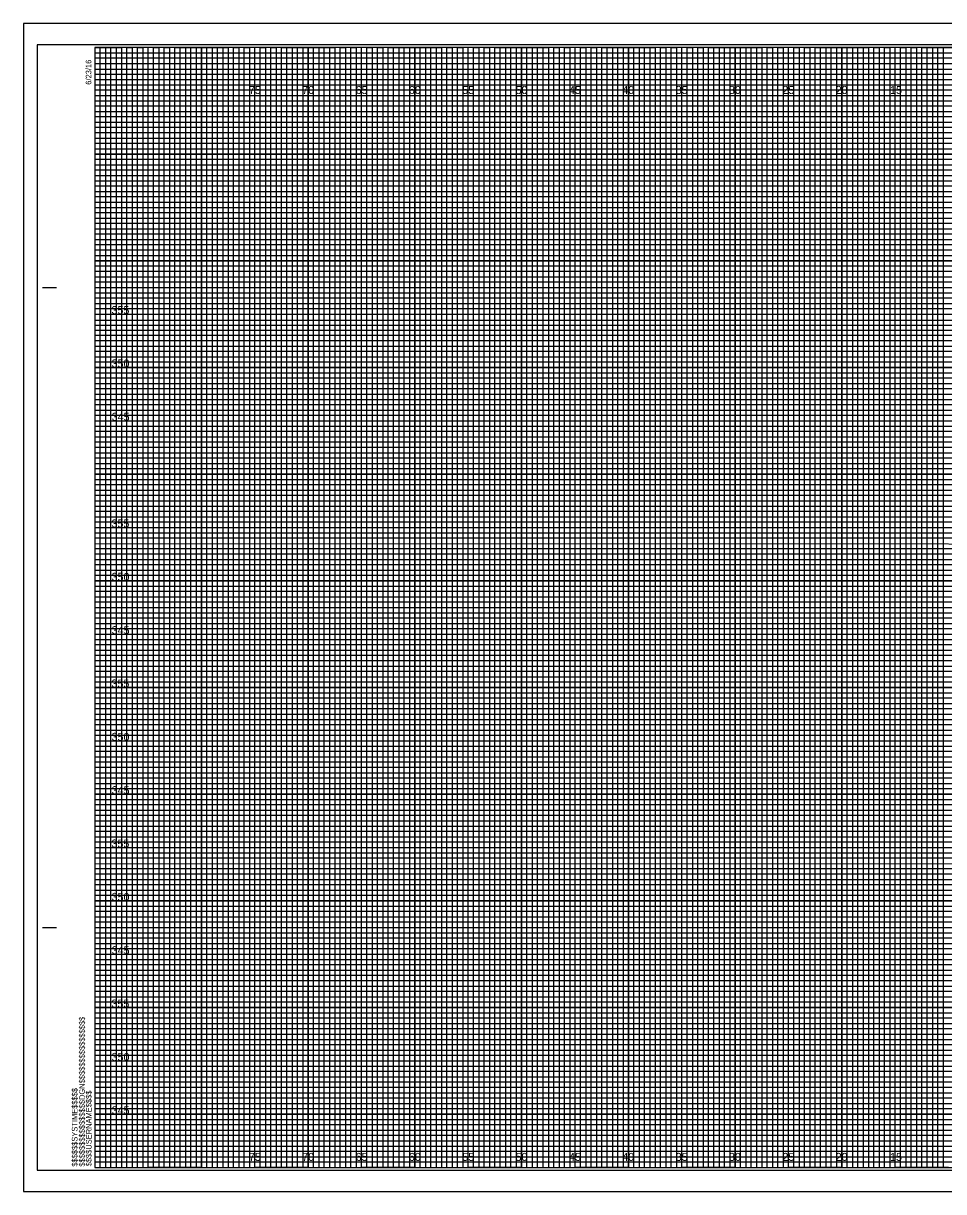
# Model space of a CAD drawing. Extents: x -7 to 166, y 218 to 327.
# Drawn here: x -6.7 to 79.5, y 217.7 to 327.2 of the extents above; entities that cross this region are included whole.
import ezdxf

# ---------------------------------------------------------------- set-up
doc = ezdxf.new("R2010")
doc.units = 0
for name, color, linetype in [('Prop XS Elevation Labels', 7, 'Continuous'), ('Prop XS Offset Labels', 7, 'Continuous'), ('Sheet Cross Section CELL', 7, 'Continuous'), ('Sheet Cross Section Grid Major CELL', 7, 'Continuous'), ('Sheet Cross Section Grid Middle CELL', 7, 'Continuous'), ('Sheet Cross Section Grid Minor 1 CELL', 7, 'Continuous'), ('Sheet Cross Section Grid Minor 2 CELL', 7, 'Continuous'), ('Sheet Cutting Line CELL', 7, 'Continuous'), ('Sheet DOT Grid CELL', 7, 'Continuous'), ('Sheet Plot Border Inside CELL', 7, 'Continuous'), ('Sheet Plot Border Outside CELL', 7, 'Continuous')]:
    doc.layers.add(name, color=color, linetype=linetype)

msp = doc.modelspace()

# ---------------------------------------------------------------- linework, layer by layer
at = {"layer": 'Sheet Cross Section CELL'}
for p, q in [((-4.9, 302.5), (-3.65, 302.5)), ((-4.85, 302.5), (-3.6, 302.5)), ((-4.9, 242.5), (-3.65, 242.5)), ((-4.85, 242.5), (-3.6, 242.5)), ((0, 220), (0, 220)), ((0, 220), (0, 220)), ((0, 220), (0, 220)), ((0, 220), (0, 220)), ((0, 220), (0, 220)), ((0, 220), (0, 220)), ((0, 220), (0, 220))]:
    msp.add_line(p, q, dxfattribs=at)
msp.add_lwpolyline([(160, 325), (0, 325), (0, 220), (160, 220)], close=True, dxfattribs=at)
at = {"layer": 'Sheet Cross Section Grid Major CELL'}
for p, q in [((5, 325), (0, 325)), ((5, 220), (5, 325)), ((15, 325), (10, 325)), ((10, 325), (10, 220)), ((15, 220), (15, 325)), ((25, 325), (20, 325)), ((20, 325), (20, 220)), ((25, 220), (25, 325)), ((35, 325), (30, 325)), ((30, 325), (30, 220)), ((35, 220), (35, 325)), ((45, 325), (40, 325)), ((40, 325), (40, 220)), ((45, 220), (45, 325)), ((55, 325), (50, 325)), ((50, 325), (50, 220)), ((55, 220), (55, 325)), ((65, 325), (60, 325)), ((60, 325), (60, 220)), ((65, 220), (65, 325)), ((75, 325), (70, 325)), ((70, 325), (70, 220)), ((75, 220), (75, 325)), ((10, 220), (5, 220)), ((20, 220), (15, 220)), ((30, 220), (25, 220)), ((40, 220), (35, 220)), ((50, 220), (45, 220)), ((60, 220), (55, 220)), ((70, 220), (65, 220)), ((80, 220), (75, 220))]:
    msp.add_line(p, q, dxfattribs=at)
for points in [[(0, 320), (160, 320), (160, 315), (0, 315)], [(0, 310), (160, 310), (160, 305), (0, 305)], [(0, 300), (160, 300), (160, 295), (0, 295)], [(0, 290), (160, 290), (160, 285), (0, 285)], [(0, 280), (160, 280), (160, 275), (0, 275)], [(0, 270), (160, 270), (160, 265), (0, 265)], [(0, 260), (160, 260), (160, 255), (0, 255)], [(0, 250), (160, 250), (160, 245), (0, 245)], [(0, 240), (160, 240), (160, 235), (0, 235)], [(0, 230), (160, 230), (160, 225), (0, 225)]]:
    msp.add_lwpolyline(points, dxfattribs=at)
at = {"layer": 'Sheet Cross Section Grid Middle CELL'}
for points in [[(0, 325), (2.5, 325), (2.5, 220), (7.5, 220), (7.5, 325), (12.5, 325), (12.5, 220), (17.5, 220), (17.5, 325), (22.5, 325), (22.5, 220), (27.5, 220), (27.5, 325), (32.5, 325), (32.5, 220), (37.5, 220), (37.5, 325), (42.5, 325), (42.5, 220), (47.5, 220), (47.5, 325), (52.5, 325), (52.5, 220), (57.5, 220), (57.5, 325), (62.5, 325), (62.5, 220), (67.5, 220), (67.5, 325), (72.5, 325), (72.5, 220), (77.5, 220), (77.5, 325), (82.5, 325)], [(0, 322.5), (137.5, 322.5)], [(0, 312.5), (160, 312.5), (160, 317.5), (0, 317.5)], [(0, 302.5), (160, 302.5), (160, 307.5), (0, 307.5)], [(0, 292.5), (160, 292.5), (160, 297.5), (0, 297.5)], [(0, 282.5), (160, 282.5), (160, 287.5), (0, 287.5)], [(0, 272.5), (160, 272.5), (160, 277.5), (0, 277.5)], [(0, 262.5), (160, 262.5), (160, 267.5), (0, 267.5)], [(0, 252.5), (160, 252.5), (160, 257.5), (0, 257.5)], [(0, 242.5), (160, 242.5), (160, 247.5), (0, 247.5)], [(0, 232.5), (160, 232.5), (160, 237.5), (0, 237.5)], [(0, 222.5), (160, 222.5), (160, 227.5), (0, 227.5)]]:
    msp.add_lwpolyline(points, dxfattribs=at)
at = {"layer": 'Sheet Cross Section Grid Minor 1 CELL'}
for p, q in [((0, 324.5), (130, 324.5)), ((130, 323.99), (0, 323.99)), ((0, 323.99), (0, 323.5)), ((0, 323.5), (130, 323.5)), ((130, 322.94), (0, 322.94)), ((0, 322.94), (0, 322)), ((0, 322), (160, 322))]:
    msp.add_line(p, q, dxfattribs=at)
for points in [[(0, 321.5), (135, 321.5), (160, 321.5), (160, 321), (0, 321)], [(0, 320.5), (160, 320.5), (160, 319.5), (0, 319.5)], [(0, 319), (160, 319), (160, 318.5), (0, 318.49)], [(0, 318), (160, 318), (160, 317), (0, 317)], [(0, 316.5), (160, 316.5), (160, 316), (0, 316)], [(0, 315.5), (160, 315.5), (160, 314.5), (0, 314.5)], [(0, 314), (160, 314), (160, 313.5), (0, 313.5)], [(0, 313), (160, 313), (160, 312), (0, 312)], [(0, 311.5), (160, 311.5), (160, 311), (0, 311)], [(0, 310.5), (160, 310.5), (160, 309.5), (0, 309.5)], [(0, 309), (160, 309), (160, 308.5), (0, 308.5)], [(0, 308), (160, 308), (160, 306.98), (160, 306.5), (160, 306), (0, 306)], [(0, 307), (160, 307), (160, 306.5), (0, 306.5)], [(0, 305.5), (160, 305.5), (160, 304.5), (0, 304.51)], [(0, 304.51), (160, 304.5), (160, 304), (0, 304)], [(0, 303.5), (160, 303.5), (160, 303), (0, 303)], [(0, 302), (160, 302), (160, 301.5), (0, 301.5)], [(0, 301), (160, 301), (160, 300.5), (0, 300.5)], [(-0.04, 299.44), (160, 299.44), (160, 298.94), (-0.04, 298.94)], [(0, 298.5), (160, 298.5), (160, 298), (0, 298)], [(0, 297), (160, 297), (160, 296.5), (0, 296.5)], [(0, 296), (160, 296), (160, 295.5), (0, 295.5)], [(0, 294.5), (160, 294.5), (160, 294), (0, 294)], [(0, 293.5), (160, 293.5), (160, 293), (0, 293)], [(0, 292), (160, 292), (160, 291.5), (0, 291.5)], [(0, 291), (160, 291), (160, 290.5), (0, 290.5)], [(0, 289.5), (160, 289.5), (160, 288.99), (0, 289)], [(0, 288.5), (160, 288.5), (160, 288), (0, 288)], [(0, 287), (160, 287), (160, 286.5), (0, 286.5)], [(0, 286), (160, 286), (160, 285.5), (0, 285.5)], [(0, 284.5), (160, 284.5), (160, 284), (0, 284)], [(0, 283.5), (160, 283.5), (160, 283), (0, 283)], [(0, 282), (160, 282), (160, 281.5), (0, 281.5)], [(0, 281), (160, 281), (160, 280.5), (0, 280.5)], [(0, 279.5), (160, 279.5), (160, 279), (0, 279)], [(0, 278.5), (160.03, 278.45), (160, 278), (0, 278)], [(0, 277), (160, 277), (160, 276.5), (0, 276.5)], [(0, 276), (160, 276), (160, 275.5), (0, 275.5)], [(0, 274.5), (160, 274.5), (160, 274), (0, 274)], [(0, 273.5), (160, 273.5), (160, 273), (0, 273)], [(0, 272), (160, 272), (160, 271.5), (0, 271.5)], [(0, 271), (160, 271), (160, 270.5), (0, 270.5)], [(0, 269.5), (160, 269.5), (160, 269), (0, 269)], [(0, 268.5), (160, 268.5), (160, 268), (0, 268)], [(0, 267), (160, 267), (160, 266.5), (0, 266.5)], [(0, 266), (160, 266), (160, 265.5), (0, 265.5)], [(0, 264.5), (160, 264.5), (160, 264), (0, 264)], [(0, 263.5), (160, 263.5), (160, 263), (0, 263)], [(0, 262), (160, 262), (160, 261.5), (0, 261.5)], [(0, 261), (160, 261), (160, 260.5), (0, 260.5)], [(0, 259.5), (160, 259.5), (160, 258.99), (0, 259)], [(0, 258.5), (160, 258.5), (160, 258), (0, 258)], [(0, 257), (160, 257), (160, 256.5), (0, 256.5)], [(0, 256), (160, 256), (160, 255.5), (0, 255.5)], [(0, 254.5), (160, 254.5), (160, 254), (0, 254)], [(0, 253.5), (160, 253.5), (160, 253), (0, 253)], [(0, 252), (160, 252), (160, 251.5), (0, 251.5)], [(0, 251), (160, 251), (160, 250.5), (0, 250.5)], [(0, 249.5), (160, 249.5), (160, 249), (0, 249)], [(0, 248.5), (160.03, 248.46), (160, 248), (0, 248)], [(0, 247), (160, 247), (160, 246.5), (0, 246.5)], [(0, 246), (160, 246), (160, 245.5), (0, 245.5)], [(0, 244.5), (160, 244.5), (160, 244), (0, 244)], [(0, 243.5), (160, 243.5), (160, 243), (0, 243)], [(0, 242), (160, 242), (160, 241.5), (0, 241.5)], [(0, 241), (160, 241), (160, 240.5), (0, 240.5)], [(0, 239.5), (160, 239.5), (160, 239), (0, 239)], [(0, 238.5), (160, 238.5), (160, 238), (0, 238)], [(0, 237), (160, 237), (160, 236.5), (0, 236.5)], [(0, 236), (160, 236), (160, 235.5), (0, 235.5)], [(0, 234.5), (160, 234.5), (160, 234), (0, 234)], [(0, 233.5), (160, 233.5), (160, 233), (0, 233)], [(0, 232), (160, 232), (160, 231.5), (0, 231.5)], [(0, 231), (160, 231), (160, 230.5), (0, 230.5)], [(0, 229.5), (160, 229.5), (160, 229), (0, 229)], [(0, 228.5), (160, 228.5), (160, 228), (0, 228)], [(0, 227), (160, 227), (160, 226.5), (0, 226.5)], [(0, 226), (160, 226), (160, 225.5), (0, 225.5)], [(0, 224.5), (160, 224.5), (160, 224), (0, 224)], [(0, 223.5), (160, 223.5), (160, 223), (0, 223)], [(0, 222), (160, 222), (160, 221.5), (0, 221.5)], [(0, 221), (160, 221), (160, 220.5), (0, 220.5)]]:
    msp.add_lwpolyline(points, dxfattribs=at)
at = {"layer": 'Sheet Cross Section Grid Minor 2 CELL'}
for points in [[(0, 220), (0.5, 220), (0.5, 325), (1, 325), (1, 220)], [(1, 220), (1.5, 220), (1.5, 325), (2, 325), (2, 220)], [(2.5, 220), (3, 220), (3, 325), (3.5, 325), (3.5, 220)], [(3.5, 220), (4, 220), (4, 325), (4.5, 325), (4.5, 220)], [(5, 220), (5.5, 220), (5.5, 325), (6, 325), (6, 220)], [(6, 220), (6.5, 220), (6.5, 325), (7, 325), (7, 220)], [(7.5, 220), (8, 220), (8, 325), (8.5, 325), (8.5, 220)], [(8.5, 220), (9, 220), (9, 325), (9.5, 325), (9.5, 220)], [(10, 220), (10.5, 220), (10.5, 325), (11, 325), (11, 220)], [(11, 220), (11.5, 220), (11.5, 325), (12, 325), (12, 220)], [(12.5, 220), (13, 220), (13, 325), (13.5, 325), (13.5, 220)], [(13.5, 220), (14, 220), (14, 325), (14.5, 325), (14.5, 220)], [(15, 220), (15.5, 220), (15.5, 325), (16, 325), (16, 220)], [(16, 220), (16.5, 220), (16.5, 325), (17, 325), (17, 220)], [(17.5, 220), (18, 220), (18, 325), (18.5, 325), (18.5, 220)], [(18.5, 220), (19, 220), (19, 325), (19.5, 325), (19.5, 220)], [(20, 220), (20.5, 220), (20.5, 325), (21, 325), (21, 220)], [(21, 220), (21.5, 220), (21.5, 325), (22, 325), (22, 220)], [(22.5, 220), (23, 220), (23, 325), (23.5, 325), (23.5, 220)], [(23.5, 220), (24, 220), (24, 325), (24.5, 325), (24.5, 220)], [(25, 220), (25.5, 220), (25.5, 325), (26, 325), (26, 220)], [(26, 220), (26.5, 220), (26.5, 325), (27, 325), (27, 220)], [(27.5, 220), (28, 220), (28, 325), (28.5, 325), (28.5, 220)], [(28.5, 220), (29, 220), (29, 325), (29.5, 325), (29.5, 220)], [(30, 220), (30.5, 220), (30.5, 325), (31, 325), (31, 220)], [(31, 220), (31.5, 220), (31.5, 325), (32, 325), (32, 220)], [(32.5, 220), (33, 220), (33, 325), (33.5, 325), (33.5, 220)], [(33.5, 220), (34, 220), (34, 325), (34.5, 325), (34.5, 220)], [(35, 220), (35.5, 220), (35.5, 325), (36, 325), (36, 220)], [(36, 220), (36.5, 220), (36.5, 325), (37, 325), (37, 220)], [(37.5, 220), (38, 220), (38, 325), (38.5, 325), (38.5, 220)], [(38.5, 220), (39, 220), (39, 325), (39.5, 325), (39.5, 220)], [(40, 220), (40.5, 220), (40.5, 325), (41, 325), (41, 220)], [(41, 220), (41.5, 220), (41.5, 325), (42, 325), (42, 220)], [(42.5, 220), (43, 220), (43, 325), (43.5, 325), (43.5, 220)], [(43.5, 220), (44, 220), (44, 325), (44.5, 325), (44.5, 220)], [(45, 220), (45.5, 220), (45.5, 325), (46, 325), (46, 220)], [(46, 220), (46.5, 220), (46.5, 325), (47, 325), (47, 220)], [(47.5, 220), (48, 220), (48, 325), (48.5, 325), (48.5, 220)], [(48.5, 220), (49, 220), (49, 325), (49.5, 325), (49.5, 220)], [(50, 220), (50.5, 220), (50.5, 325), (51, 325), (51, 220)], [(51, 220), (51.5, 220), (51.5, 325), (52, 325), (52, 220)], [(52.5, 220), (53, 220), (53, 325), (53.5, 325), (53.5, 220)], [(53.5, 220), (54, 220), (54, 325), (54.5, 325), (54.5, 220)], [(55, 220), (55.5, 220), (55.5, 325), (56, 325), (56, 220)], [(56, 220), (56.5, 220), (56.5, 325), (57, 325), (57, 220)], [(57.5, 220), (58, 220), (58, 325), (58.5, 325), (58.5, 220)], [(58.5, 220), (59, 220), (59, 325), (59.5, 325), (59.5, 220)], [(60, 220), (60.5, 220), (60.5, 325), (61, 325), (61, 220)], [(61, 220), (61.5, 220), (61.5, 325), (62, 325), (62, 220)], [(62.5, 220), (63, 220), (63, 325), (63.5, 325), (63.5, 220)], [(63.5, 220), (64, 220), (64, 325), (64.5, 325), (64.5, 220)], [(65, 220), (65.5, 220), (65.5, 325), (66, 325), (66, 220)], [(66, 220), (66.5, 220), (66.5, 325), (67, 325), (67, 220)], [(67.5, 220), (68, 220), (68, 325), (68.5, 325), (68.5, 220)], [(68.5, 220), (69, 220), (69, 325), (69.5, 325), (69.5, 220)], [(70, 220), (70.5, 220), (70.5, 325), (71, 325), (71, 220)], [(71, 220), (71.5, 220), (71.5, 325), (72, 325), (72, 220)], [(72.5, 220), (73, 220), (73, 325), (73.5, 325), (73.5, 220)], [(73.5, 220), (74, 220), (74, 325), (74.5, 325), (74.5, 220)], [(75, 220), (75.5, 220), (75.5, 325), (76, 325), (76, 220)], [(76, 220), (76.5, 220), (76.5, 325), (77, 325), (77, 220)], [(77.5, 220), (78, 220), (78, 325), (78.5, 325), (78.5, 220)], [(78.5, 220), (79, 220), (79, 325), (79.5, 325), (79.5, 220)]]:
    msp.add_lwpolyline(points, dxfattribs=at)
at = {"layer": 'Sheet Cutting Line CELL'}
for p, q in [((161.65, 327.25), (-6.7, 327.25)), ((-6.7, 327.25), (-6.7, 217.75)), ((-6.7, 217.75), (161.65, 217.75))]:
    msp.add_line(p, q, dxfattribs=at)
at = {"layer": 'Sheet DOT Grid CELL'}
for p, q in [((5, 220), (5, 325)), ((10, 220), (10, 325)), ((15, 220), (15, 325)), ((20, 220), (20, 325)), ((25, 220), (25, 325)), ((30, 220), (30, 325)), ((35, 220), (35, 325)), ((40, 220), (40, 325)), ((45, 220), (45, 325)), ((50, 220), (50, 325)), ((55, 220), (55, 325)), ((60, 220), (60, 325)), ((65, 220), (65, 325)), ((70, 220), (70, 325)), ((75, 220), (75, 325)), ((0, 320), (160, 320)), ((0, 315), (160, 315)), ((0, 310), (160, 310)), ((0, 305), (160, 305)), ((0, 300), (160, 300)), ((0, 295), (160, 295)), ((0, 290), (160, 290)), ((0, 285), (160, 285)), ((0, 280), (160, 280)), ((0, 275), (160, 275)), ((0, 270), (160, 270)), ((0, 265), (160, 265)), ((0, 260), (160, 260)), ((0, 255), (160, 255)), ((0, 250), (160, 250)), ((0, 245), (160, 245)), ((0, 240), (160, 240)), ((0, 235), (160, 235)), ((0, 230), (160, 230)), ((0, 225), (160, 225))]:
    msp.add_line(p, q, dxfattribs=at)
at = {"layer": 'Sheet Plot Border Inside CELL'}
msp.add_lwpolyline([(-5.4, 219.75), (161.2, 219.75), (161.2, 325.25), (-5.4, 325.25)], close=True, dxfattribs=at)
at = {"layer": 'Sheet Plot Border Outside CELL'}
msp.add_lwpolyline([(-6.7, 217.75), (161.65, 217.75), (161.65, 327.25), (-6.7, 327.25)], close=True, dxfattribs=at)

# ---------------------------------------------------------------- texts
at = {"layer": 'Prop XS Elevation Labels'}
for s, p in [('355', (1.56, 300)), ('350', (1.57, 295)), ('345', (1.58, 290)), ('355', (1.56, 280)), ('350', (1.57, 275)), ('345', (1.58, 270)), ('355', (1.56, 265)), ('350', (1.57, 260)), ('345', (1.58, 255)), ('355', (1.56, 250)), ('350', (1.57, 245)), ('345', (1.58, 240)), ('355', (1.56, 235)), ('350', (1.57, 230)), ('345', (1.58, 225))]:
    msp.add_text(s, height=0.75, dxfattribs=at).set_placement(p)
at = {"layer": 'Prop XS Offset Labels'}
for s, p in [('75', (14.44, 320.63)), ('70', (19.43, 320.63)), ('65', (24.44, 320.63)), ('60', (29.43, 320.63)), ('55', (34.44, 320.63)), ('50', (39.43, 320.63)), ('45', (44.44, 320.63)), ('40', (49.43, 320.63)), ('35', (54.44, 320.63)), ('30', (59.43, 320.63)), ('25', (64.44, 320.63)), ('20', (69.43, 320.63)), ('15', (74.53, 320.63)), ('75', (14.44, 220.63)), ('70', (19.43, 220.63)), ('65', (24.44, 220.63)), ('60', (29.43, 220.63)), ('55', (34.44, 220.63)), ('50', (39.43, 220.63)), ('45', (44.44, 220.63)), ('40', (49.43, 220.63)), ('35', (54.44, 220.63)), ('30', (59.43, 220.63)), ('25', (64.44, 220.63)), ('20', (69.43, 220.63)), ('15', (74.53, 220.63))]:
    msp.add_text(s, height=0.75, dxfattribs=at).set_placement(p)
at = {"layer": 'Sheet Cross Section CELL'}
for s, p in [('6/23/16', (-0.33, 321.5)), ('$$$$$$$$$$$$$$$$DGN$$$$$$$$$$$$$$$$', (-0.94, 220.09)), ('$$$$$$SYSTIME$$$$$', (-1.63, 220.09)), ('$$$$USERNAME$$$$', (-0.31, 220.12))]:
    msp.add_text(s, height=0.525, rotation=90, dxfattribs=at).set_placement(p)

doc.saveas('drawing.dxf')
